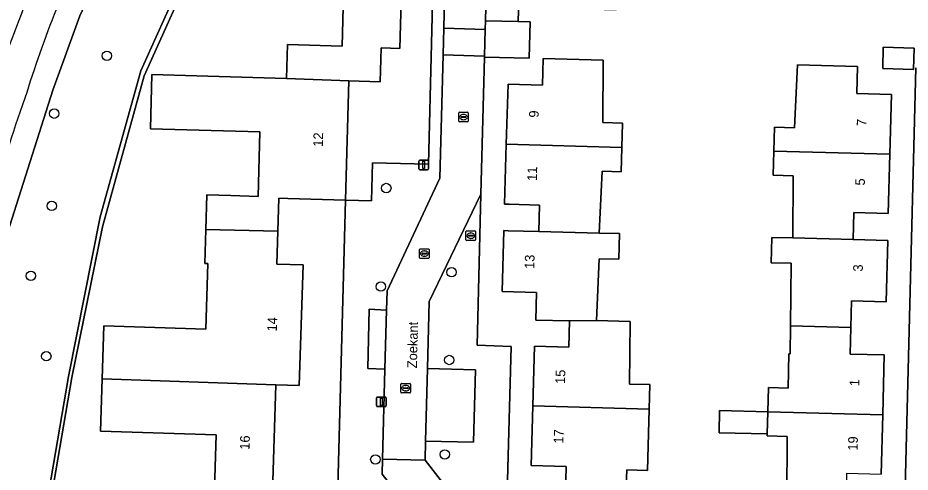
# Model space of a CAD drawing. Extents: x 162082 to 163401, y 388089 to 388636.
# Drawn here: x 162155.2 to 162248, y 388192.8 to 388240.1 of the extents above; entities that cross this region are included whole.
import ezdxf

# ---------------------------------------------------------------- set-up
doc = ezdxf.new("R2010")
doc.units = 0
for name, color, linetype in [('IMGEO_Berm_groen', 7, 'Continuous'), ('IMGEO_Boom', 7, 'Continuous'), ('IMGEO_Brandkraan', 7, 'Continuous'), ('IMGEO_Erf', 7, 'Continuous'), ('IMGEO_Fietspad_gesloten', 7, 'Continuous'), ('IMGEO_Groenvoorziening', 7, 'Continuous'), ('IMGEO_Kolk', 7, 'Continuous'), ('IMGEO_Lichtmast', 7, 'Continuous'), ('IMGEO_Muur', 7, 'Continuous'), ('IMGEO_Openbare_ruimte_label', 7, 'Continuous'), ('IMGEO_Pand', 7, 'Continuous'), ('IMGEO_Pand_nummerreeks', 7, 'Continuous'), ('IMGEO_Parkeervlak_open', 7, 'Continuous'), ('IMGEO_Rijbaan_lokaal_open', 7, 'Continuous'), ('IMGEO_Voetpad_open', 7, 'Continuous')]:
    doc.layers.add(name, color=color, linetype=linetype)

msp = doc.modelspace()

# ---------------------------------------------------------------- linework, layer by layer
at = {"layer": 'IMGEO_Berm_groen'}
for points in [[(162157.762, 388186.972), (162160.453, 388202.779), (162163.757, 388219.4), (162167.977, 388234.595), (162172.103, 388243.782), (162172.009, 388243.827), (162174.687, 388249.789), (162174.799, 388249.786), (162177.085, 388254.875), (162185.012, 388266.817), (162192.618, 388276.468), (162195.788, 388280.075), (162202.082, 388286.205), (162199.498, 388288.679), (162206.339, 388296.126), (162204.757, 388297.619), (162216.729, 388310.598)], [(162207.657, 388306.004), (162193.849, 388291.667), (162195.833, 388289.739), (162185.601, 388278.37), (162179.303, 388271.066), (162173.82, 388263.104), (162169.541, 388255.855), (162166.315, 388250), (162165.112, 388247.818), (162161.634, 388240.291), (162158.829, 388232.574), (162153.616, 388216.204), (162152.635, 388208.277), (162153.36, 388204.265), (162153.504, 388199.591), (162151.506, 388186.435)]]:
    msp.add_lwpolyline(points, dxfattribs=at)
msp.add_arc((162273.166, 388193.916), 126.504, 155.33064, 165.20021, dxfattribs=at)
at = {"layer": 'IMGEO_Boom'}
for centre in [(162164.44, 388236.151), (162158.966, 388230.129), (162193.502, 388222.392), (162158.707, 388220.536), (162156.535, 388213.27), (162200.287, 388213.64), (162192.947, 388212.142), (162158.143, 388204.9), (162200.053, 388204.506), (162199.581, 388194.687), (162192.363, 388194.159)]:
    msp.add_circle(centre, 0.489, dxfattribs=at)
at = {"layer": 'IMGEO_Brandkraan'}
for p, q in [((162201.862, 388217.937), (162202.714, 388217.937)), ((162201.787, 388217.011), (162201.787, 388217.863)), ((162202.046, 388217.431), (162202.046, 388217.443)), ((162202.484, 388217.394), (162202.086, 388217.394)), ((162202.089, 388217.48), (162202.487, 388217.48)), ((162202.298, 388217.157), (162202.273, 388217.157)), ((162202.275, 388217.717), (162202.3, 388217.717)), ((162202.53, 388217.443), (162202.53, 388217.431)), ((162202.788, 388217.863), (162202.788, 388217.011)), ((162202.714, 388216.937), (162201.862, 388216.937))]:
    msp.add_line(p, q, dxfattribs=at)
for points in [[(162201.862, 388217.937), (162202.714, 388217.937)], [(162201.787, 388217.011), (162201.787, 388217.863)], [(162202.788, 388217.863), (162202.788, 388217.011)], [(162202.714, 388216.937), (162201.862, 388216.937)]]:
    msp.add_lwpolyline(points, dxfattribs=at)
for centre, radius, start, end in [((162201.864, 388217.861), 0.0765, 91.55205, 178.44795), ((162201.864, 388217.861), 0.0765, 91.55205, 178.44795), ((162202.712, 388217.861), 0.0765, 1.55205, 88.44795), ((162202.712, 388217.861), 0.0765, 1.55205, 88.44795), ((162201.864, 388217.013), 0.0765, 181.55205, 268.44795), ((162201.864, 388217.013), 0.0765, 181.55205, 268.44795), ((162202.086, 388217.44), 0.0403, 85.87752, 175.75265), ((162202.083, 388217.43), 0.0366, 178.93798, 274.71019), ((162202.487, 388217.437), 0.043, 264.86636, 352.45326), ((162202.491, 388217.442), 0.0386, 1.73085, 96.63898), ((162202.712, 388217.013), 0.0765, 271.55205, 358.44795), ((162202.712, 388217.013), 0.0765, 271.55205, 358.44795)]:
    msp.add_arc(centre, radius, start, end, dxfattribs=at)
for centre, major_axis, ratio, start_param, end_param in [((162202.274, 388217.437), (-0.387, 0.002), 0.722429, 4.712389, 7.853982), ((162202.299, 388217.437), (-0.39, 0.002), 0.717154, 1.570796, 4.712389)]:
    msp.add_ellipse(centre, major_axis=major_axis, ratio=ratio, start_param=start_param, end_param=end_param, dxfattribs=at)
at = {"layer": 'IMGEO_Erf'}
for points in [[(162195.256, 388249.225), (162194.905, 388236.916), (162192.964, 388236.972), (162192.864, 388233.447), (162189.615, 388233.54), (162189.261, 388221.138), (162191.96, 388221.062), (162192.072, 388225.007), (162197.898, 388224.865), (162198.526, 388250)], [(162175.609, 388189.983), (162175.823, 388196.73), (162163.788, 388197.112), (162163.96, 388202.542), (162164.135, 388208.05), (162174.724, 388207.714), (162174.94, 388214.538), (162174.621, 388214.548), (162174.733, 388218.078), (162174.847, 388221.689), (162177.326, 388221.61), (162180.165, 388221.52), (162180.356, 388228.234), (162168.964, 388228.559), (162169.125, 388234.186), (162183.13, 388233.787), (162183.23, 388237.319), (162188.906, 388237.157), (162189.099, 388243.93)], [(162172.591, 388243.552), (162168.323, 388234.056), (162163.98, 388218.368), (162160.807, 388202.671), (162158.079, 388186.902)], [(162207.325, 388243.257), (162207.23, 388239.701), (162208.459, 388239.668), (162208.358, 388235.884), (162203.706, 388236.008), (162203.345, 388221.743), (162202.944, 388206.041), (162206.472, 388205.907), (162206.087, 388190.715)], [(162212.126, 388190.638), (162212.205, 388193.419), (162208.567, 388193.522), (162208.742, 388199.747), (162208.916, 388205.928), (162212.49, 388205.827), (162212.568, 388208.567), (162209.049, 388208.666), (162209.129, 388211.517), (162205.541, 388211.618), (162205.72, 388217.964), (162206.19, 388217.951), (162209.362, 388217.862), (162209.44, 388220.62), (162206.279, 388220.709), (162205.809, 388220.722), (162205.985, 388226.955), (162206.16, 388233.186), (162209.739, 388233.086), (162209.818, 388235.864), (162214.817, 388235.723), (162216.069, 388235.688), (162216.039, 388229.194), (162218.074, 388229.137), (162218.002, 388226.614), (162217.931, 388224.091), (162215.94, 388224.147), (162215.639, 388217.715), (162217.77, 388217.655), (162217.695, 388214.979), (162215.648, 388215.037), (162215.366, 388208.617), (162218.86, 388208.519), (162218.791, 388202.001), (162220.92, 388201.941), (162220.849, 388199.408), (162220.778, 388196.875), (162220.669, 388193.016), (162218.521, 388193.077), (162218.402, 388190.462)], [(162235.149, 388190.087), (162235.185, 388196.562), (162233.108, 388196.617), (162233.113, 388196.814), (162228.113, 388196.946), (162228.174, 388199.263), (162233.174, 388199.131), (162233.241, 388201.645), (162235.283, 388201.591), (162235.378, 388205.15), (162235.492, 388205.147), (162235.533, 388208.057), (162235.626, 388214.563), (162233.545, 388214.618), (162233.615, 388217.262), (162235.78, 388217.204), (162235.835, 388223.667), (162233.745, 388223.723), (162233.811, 388226.22), (162233.877, 388228.718), (162235.958, 388228.663), (162236.257, 388235.211), (162237.516, 388235.178), (162242.514, 388235.045), (162242.439, 388232.224), (162246.039, 388232.128), (162245.874, 388225.902), (162245.711, 388219.759), (162242.124, 388219.854), (162242.049, 388217.026), (162245.661, 388216.931), (162245.492, 388210.56), (162241.893, 388210.655), (162241.819, 388207.89), (162241.746, 388205.126), (162245.299, 388205.032), (162245.135, 388198.815), (162244.971, 388192.631)], [(162247.444, 388189.812), (162248.593, 388234.883)], [(162188.209, 388182.234), (162189.261, 388221.138), (162183.262, 388221.309), (162182.319, 388221.336), (162182.211, 388217.911), (162182.102, 388214.475), (162184.853, 388214.387), (162184.456, 388201.851), (162182.005, 388201.929), (162181.617, 388189.702)]]:
    msp.add_lwpolyline(points, dxfattribs=at)
msp.add_lwpolyline([(162245.129, 388234.822), (162245.188, 388237.034), (162248.407, 388236.948), (162248.348, 388234.736)], close=True, dxfattribs=at)
at = {"layer": 'IMGEO_Fietspad_gesloten'}
for centre, radius, start, end in [((162272.303, 388195.984), 121.751, 153.66232, 162.91897), ((162273.166, 388193.916), 126.504, 155.33064, 165.20021), ((162244.129, 388199.115), 94.049, 159.69961, 173.99707)]:
    msp.add_arc(centre, radius, start, end, dxfattribs=at)
at = {"layer": 'IMGEO_Groenvoorziening'}
msp.add_lwpolyline([(162156.818, 388168.551), (162155.992, 388168.648), (162155.548, 388168.732), (162155.641, 388169.499), (162149.29, 388170.484), (162151.506, 388186.435), (162153.504, 388199.591), (162153.36, 388204.265), (162152.635, 388208.277), (162153.616, 388216.204), (162158.829, 388232.574), (162161.634, 388240.291), (162165.112, 388247.818), (162166.315, 388250), (162169.541, 388255.855), (162173.82, 388263.104), (162179.303, 388271.066), (162185.601, 388278.37), (162195.833, 388289.739), (162193.849, 388291.667), (162191.53, 388289.26)], dxfattribs=at)
for centre, radius, start, end in [((162272.303, 388195.984), 121.751, 153.66232, 162.91897), ((162244.129, 388199.115), 94.049, 159.69961, 173.99707)]:
    msp.add_arc(centre, radius, start, end, dxfattribs=at)
at = {"layer": 'IMGEO_Kolk'}
for p, q in [((162201.029, 388229.348), (162201.029, 388230.2)), ((162201.104, 388230.274), (162201.956, 388230.274)), ((162201.517, 388230.054), (162201.542, 388230.054)), ((162202.03, 388230.2), (162202.03, 388229.348)), ((162201.956, 388229.274), (162201.104, 388229.274)), ((162201.288, 388229.768), (162201.288, 388229.78)), ((162201.726, 388229.731), (162201.328, 388229.731)), ((162201.331, 388229.817), (162201.729, 388229.817)), ((162201.54, 388229.494), (162201.515, 388229.494)), ((162201.772, 388229.78), (162201.772, 388229.768)), ((162197.036, 388216.072), (162197.888, 388216.072)), ((162196.961, 388215.146), (162196.961, 388215.998)), ((162197.22, 388215.566), (162197.22, 388215.578)), ((162197.658, 388215.529), (162197.26, 388215.529)), ((162197.263, 388215.615), (162197.661, 388215.615)), ((162197.472, 388215.292), (162197.447, 388215.292)), ((162197.449, 388215.852), (162197.474, 388215.852)), ((162197.704, 388215.578), (162197.704, 388215.566)), ((162197.962, 388215.998), (162197.962, 388215.146)), ((162197.888, 388215.072), (162197.036, 388215.072)), ((162195.019, 388201.152), (162195.019, 388202.004)), ((162195.094, 388202.078), (162195.946, 388202.078)), ((162195.278, 388201.572), (162195.278, 388201.584)), ((162195.716, 388201.535), (162195.318, 388201.535)), ((162195.321, 388201.621), (162195.719, 388201.621)), ((162195.53, 388201.298), (162195.505, 388201.298)), ((162195.507, 388201.858), (162195.532, 388201.858)), ((162195.762, 388201.584), (162195.762, 388201.572)), ((162196.02, 388202.004), (162196.02, 388201.152)), ((162195.946, 388201.078), (162195.094, 388201.078))]:
    msp.add_line(p, q, dxfattribs=at)
for points in [[(162201.029, 388229.348), (162201.029, 388230.2)], [(162201.104, 388230.274), (162201.956, 388230.274)], [(162202.03, 388230.2), (162202.03, 388229.348)], [(162201.956, 388229.274), (162201.104, 388229.274)], [(162197.036, 388216.072), (162197.888, 388216.072)], [(162196.961, 388215.146), (162196.961, 388215.998)], [(162197.962, 388215.998), (162197.962, 388215.146)], [(162197.888, 388215.072), (162197.036, 388215.072)], [(162195.019, 388201.152), (162195.019, 388202.004)], [(162195.094, 388202.078), (162195.946, 388202.078)], [(162196.02, 388202.004), (162196.02, 388201.152)], [(162195.946, 388201.078), (162195.094, 388201.078)]]:
    msp.add_lwpolyline(points, dxfattribs=at)
for centre, radius, start, end in [((162201.106, 388230.198), 0.0765, 91.55205, 178.44795), ((162201.106, 388230.198), 0.0765, 91.55205, 178.44795), ((162201.954, 388230.198), 0.0765, 1.55205, 88.44795), ((162201.954, 388230.198), 0.0765, 1.55205, 88.44795), ((162201.106, 388229.35), 0.0765, 181.55205, 268.44795), ((162201.106, 388229.35), 0.0765, 181.55205, 268.44795), ((162201.328, 388229.777), 0.0403, 85.87752, 175.75265), ((162201.325, 388229.767), 0.0366, 178.93798, 274.71019), ((162201.729, 388229.774), 0.043, 264.86636, 352.45326), ((162201.733, 388229.779), 0.0386, 1.73085, 96.63898), ((162201.954, 388229.35), 0.0765, 271.55205, 358.44795), ((162201.954, 388229.35), 0.0765, 271.55205, 358.44795), ((162197.038, 388215.996), 0.0765, 91.55205, 178.44795), ((162197.038, 388215.996), 0.0765, 91.55205, 178.44795), ((162197.886, 388215.996), 0.0765, 1.55205, 88.44795), ((162197.886, 388215.996), 0.0765, 1.55205, 88.44795), ((162197.038, 388215.148), 0.0765, 181.55205, 268.44795), ((162197.038, 388215.148), 0.0765, 181.55205, 268.44795), ((162197.26, 388215.575), 0.0403, 85.87752, 175.75265), ((162197.257, 388215.565), 0.0366, 178.93798, 274.71019), ((162197.661, 388215.572), 0.043, 264.86636, 352.45326), ((162197.665, 388215.577), 0.0386, 1.73085, 96.63898), ((162197.886, 388215.148), 0.0765, 271.55205, 358.44795), ((162197.886, 388215.148), 0.0765, 271.55205, 358.44795), ((162195.096, 388202.002), 0.0765, 91.55205, 178.44795), ((162195.096, 388202.002), 0.0765, 91.55205, 178.44795), ((162195.318, 388201.581), 0.0403, 85.87752, 175.75265), ((162195.315, 388201.571), 0.0366, 178.93798, 274.71019), ((162195.719, 388201.578), 0.043, 264.86636, 352.45326), ((162195.723, 388201.583), 0.0386, 1.73085, 96.63898), ((162195.944, 388202.002), 0.0765, 1.55205, 88.44795), ((162195.944, 388202.002), 0.0765, 1.55205, 88.44795), ((162195.096, 388201.154), 0.0765, 181.55205, 268.44795), ((162195.096, 388201.154), 0.0765, 181.55205, 268.44795), ((162195.944, 388201.154), 0.0765, 271.55205, 358.44795), ((162195.944, 388201.154), 0.0765, 271.55205, 358.44795)]:
    msp.add_arc(centre, radius, start, end, dxfattribs=at)
for centre, major_axis, ratio, start_param, end_param in [((162201.516, 388229.774), (-0.387, 0.002), 0.722429, 4.712389, 7.853982), ((162201.541, 388229.774), (-0.39, 0.002), 0.717154, 1.570796, 4.712389), ((162197.448, 388215.572), (-0.387, 0.002), 0.722429, 4.712389, 7.853982), ((162197.473, 388215.572), (-0.39, 0.002), 0.717154, 1.570796, 4.712389), ((162195.506, 388201.578), (-0.387, 0.002), 0.722429, 4.712389, 7.853982), ((162195.531, 388201.578), (-0.39, 0.002), 0.717154, 1.570796, 4.712389)]:
    msp.add_ellipse(centre, major_axis=major_axis, ratio=ratio, start_param=start_param, end_param=end_param, dxfattribs=at)
at = {"layer": 'IMGEO_Lichtmast'}
for p, q in [((162196.895, 388224.397), (162196.895, 388225.197)), ((162196.895, 388225.197), (162196.895, 388224.397)), ((162196.995, 388225.297), (162197.785, 388225.297)), ((162197.785, 388225.297), (162196.995, 388225.297)), ((162197.885, 388225.197), (162197.885, 388224.397)), ((162197.885, 388224.397), (162197.885, 388225.197)), ((162197.785, 388224.297), (162196.995, 388224.297)), ((162196.995, 388224.297), (162197.785, 388224.297)), ((162192.493, 388199.757), (162192.493, 388200.557)), ((162192.493, 388200.557), (162192.493, 388199.757)), ((162192.593, 388200.657), (162193.383, 388200.657)), ((162193.383, 388200.657), (162192.593, 388200.657)), ((162193.483, 388200.557), (162193.483, 388199.757)), ((162193.483, 388199.757), (162193.483, 388200.557)), ((162193.383, 388199.657), (162192.593, 388199.657)), ((162192.593, 388199.657), (162193.383, 388199.657))]:
    msp.add_line(p, q, dxfattribs=at)
for points in [[(162197.315, 388225.172), (162197.465, 388225.172), (162197.465, 388224.422), (162197.315, 388224.422), (162197.315, 388225.172)], [(162192.913, 388200.532), (162193.063, 388200.532), (162193.063, 388199.782), (162192.913, 388199.782), (162192.913, 388200.532)]]:
    msp.add_lwpolyline(points, dxfattribs=at)
for centre, start, end in [((162196.995, 388225.197), 90, 180), ((162196.995, 388225.197), 90, 180), ((162197.785, 388225.197), 0, 90), ((162197.785, 388225.197), 360, 90), ((162196.995, 388224.397), 180, 270), ((162196.995, 388224.397), 180, 270), ((162197.785, 388224.397), 270, 0), ((162197.785, 388224.397), 270, 0), ((162192.593, 388200.557), 90, 180), ((162192.593, 388200.557), 90, 180), ((162193.383, 388200.557), 0, 90), ((162193.383, 388200.557), 360, 90), ((162192.593, 388199.757), 180, 270), ((162192.593, 388199.757), 180, 270), ((162193.383, 388199.757), 270, 0), ((162193.383, 388199.757), 270, 0)]:
    msp.add_arc(centre, 0.1, start, end, dxfattribs=at)
at = {"layer": 'IMGEO_Muur'}
msp.add_lwpolyline([(162168.323, 388234.056), (162172.591, 388243.552), (162172.103, 388243.782), (162167.977, 388234.595), (162163.757, 388219.4), (162160.453, 388202.779), (162157.762, 388186.972), (162155.641, 388169.499), (162155.548, 388168.732), (162155.992, 388168.648), (162158.079, 388186.902), (162160.807, 388202.671), (162163.98, 388218.368)], close=True, dxfattribs=at)
at = {"layer": 'IMGEO_Pand'}
for points in [[(162217.729, 388253.009), (162211.462, 388253.177), (162211.378, 388250), (162211.367, 388249.592), (162204.074, 388249.786), (162203.807, 388239.792), (162207.23, 388239.701), (162207.325, 388243.257), (162214.931, 388243.054), (162214.875, 388240.981), (162217.406, 388240.913), (162217.649, 388250)], [(162195.256, 388249.225), (162177.679, 388249.707), (162175.385, 388249.77), (162174.799, 388249.786), (162174.687, 388249.789), (162172.009, 388243.827), (162172.103, 388243.782), (162172.591, 388243.552), (162175.572, 388242.141), (162176.763, 388242.099), (162177.707, 388242.955), (162177.701, 388244.255), (162189.099, 388243.93), (162188.906, 388237.157), (162183.23, 388237.319), (162183.13, 388233.787), (162189.615, 388233.54), (162192.864, 388233.447), (162192.964, 388236.972), (162194.905, 388236.916)], [(162207.23, 388239.701), (162203.807, 388239.792), (162203.783, 388238.893), (162203.709, 388236.124), (162203.706, 388236.008), (162208.358, 388235.884), (162208.459, 388239.668)], [(162245.129, 388234.822), (162248.348, 388234.736), (162248.407, 388236.948), (162245.188, 388237.034)], [(162205.985, 388226.955), (162218.002, 388226.614), (162218.074, 388229.137), (162216.039, 388229.194), (162216.069, 388235.688), (162214.817, 388235.723), (162209.818, 388235.864), (162209.739, 388233.086), (162206.16, 388233.186)], [(162233.811, 388226.22), (162245.874, 388225.902), (162246.039, 388232.128), (162242.439, 388232.224), (162242.514, 388235.045), (162237.516, 388235.178), (162236.257, 388235.211), (162235.958, 388228.663), (162233.877, 388228.718)], [(162189.615, 388233.54), (162183.13, 388233.787), (162169.125, 388234.186), (162168.964, 388228.559), (162180.356, 388228.234), (162180.165, 388221.52), (162177.326, 388221.61), (162174.847, 388221.689), (162174.733, 388218.078), (162182.211, 388217.911), (162182.319, 388221.336), (162183.262, 388221.309), (162189.261, 388221.138)], [(162209.362, 388217.862), (162215.639, 388217.715), (162215.94, 388224.147), (162217.931, 388224.091), (162218.002, 388226.614), (162205.985, 388226.955), (162205.809, 388220.722), (162206.279, 388220.709), (162209.44, 388220.62)], [(162235.78, 388217.204), (162242.049, 388217.026), (162242.124, 388219.854), (162245.711, 388219.759), (162245.874, 388225.902), (162233.811, 388226.22), (162233.745, 388223.723), (162235.835, 388223.667)], [(162184.853, 388214.387), (162182.102, 388214.475), (162182.211, 388217.911), (162174.733, 388218.078), (162174.621, 388214.548), (162174.94, 388214.538), (162174.724, 388207.714), (162164.135, 388208.05), (162163.96, 388202.542), (162182.005, 388201.929), (162184.456, 388201.851)], [(162212.568, 388208.567), (162215.366, 388208.617), (162215.648, 388215.037), (162217.695, 388214.979), (162217.77, 388217.655), (162215.639, 388217.715), (162209.362, 388217.862), (162206.19, 388217.951), (162205.72, 388217.964), (162205.541, 388211.618), (162209.129, 388211.517), (162209.049, 388208.666)], [(162235.78, 388217.204), (162233.615, 388217.262), (162233.545, 388214.618), (162235.626, 388214.563), (162235.533, 388208.057), (162241.819, 388207.89), (162241.893, 388210.655), (162245.492, 388210.56), (162245.661, 388216.931), (162242.049, 388217.026)], [(162212.568, 388208.567), (162212.49, 388205.827), (162208.916, 388205.928), (162208.742, 388199.747), (162220.849, 388199.408), (162220.92, 388201.941), (162218.791, 388202.001), (162218.86, 388208.519), (162215.366, 388208.617)], [(162233.174, 388199.131), (162245.135, 388198.815), (162245.299, 388205.032), (162241.746, 388205.126), (162241.819, 388207.89), (162235.533, 388208.057), (162235.492, 388205.147), (162235.378, 388205.15), (162235.283, 388201.591), (162233.241, 388201.645)], [(162163.788, 388197.112), (162175.823, 388196.73), (162175.609, 388189.983), (162170.122, 388190.157), (162170.01, 388186.629), (162177.566, 388186.402), (162177.674, 388189.827), (162181.617, 388189.702), (162182.005, 388201.929), (162163.96, 388202.542)], [(162220.849, 388199.408), (162208.742, 388199.747), (162208.567, 388193.522), (162212.205, 388193.419), (162212.126, 388190.638), (162218.402, 388190.462), (162218.521, 388193.077), (162220.669, 388193.016), (162220.778, 388196.875)], [(162233.174, 388199.131), (162228.174, 388199.263), (162228.113, 388196.946), (162233.113, 388196.814)], [(162245.135, 388198.815), (162233.174, 388199.131), (162233.113, 388196.814), (162233.108, 388196.617), (162235.185, 388196.562), (162235.149, 388190.087), (162241.342, 388189.923), (162241.416, 388192.725), (162244.971, 388192.631)]]:
    msp.add_lwpolyline(points, close=True, dxfattribs=at)
at = {"layer": 'IMGEO_Parkeervlak_open'}
for points in [[(162193.526, 388209.687), (162191.729, 388209.785), (162191.567, 388203.624), (162193.366, 388203.564)], [(162197.588, 388196.062), (162202.576, 388195.956), (162202.764, 388203.494), (162197.788, 388203.634)]]:
    msp.add_lwpolyline(points, close=True, dxfattribs=at)
at = {"layer": 'IMGEO_Rijbaan_lokaal_open'}
for points in [[(162204.074, 388249.786), (162204.08, 388250), (162204.241, 388255.823), (162199.889, 388255.931), (162199.742, 388250), (162199.47, 388239.004), (162203.783, 388238.893), (162203.807, 388239.792)], [(162203.783, 388238.893), (162199.47, 388239.004), (162199.401, 388236.235), (162203.709, 388236.124)], [(162203.345, 388221.743), (162203.706, 388236.008), (162203.709, 388236.124), (162199.401, 388236.235), (162199.084, 388223.422), (162193.579, 388211.712), (162193.526, 388209.687), (162193.366, 388203.564), (162193.114, 388194.2), (162197.54, 388194.081), (162197.588, 388196.062), (162197.788, 388203.634), (162197.969, 388210.593)], [(162247.424, 388188.529), (162206.058, 388189.507), (162201.028, 388189.626), (162197.54, 388194.081), (162193.114, 388194.2), (162193.072, 388192.624), (162198.816, 388185.29), (162202.738, 388185.187), (162208.745, 388185.028), (162225.315, 388184.591), (162237.373, 388184.273), (162247.313, 388184.011)]]:
    msp.add_lwpolyline(points, close=True, dxfattribs=at)
at = {"layer": 'IMGEO_Voetpad_open'}
for points in [[(162199.742, 388250), (162199.889, 388255.931), (162199.959, 388258.772), (162199.97, 388259.135), (162198.755, 388259.165), (162198.526, 388250), (162197.898, 388224.865), (162192.072, 388225.007), (162191.96, 388221.062), (162189.261, 388221.138), (162188.209, 388182.234), (162198.727, 388181.955), (162198.816, 388185.29), (162193.072, 388192.624), (162193.114, 388194.2), (162193.366, 388203.564), (162191.567, 388203.624), (162191.729, 388209.785), (162193.526, 388209.687), (162193.579, 388211.712), (162199.084, 388223.422), (162199.401, 388236.235), (162199.47, 388239.004)], [(162206.472, 388205.907), (162202.944, 388206.041), (162203.345, 388221.743), (162197.969, 388210.593), (162197.788, 388203.634), (162202.764, 388203.494), (162202.576, 388195.956), (162197.588, 388196.062), (162197.54, 388194.081), (162201.028, 388189.626), (162206.058, 388189.507), (162206.087, 388190.715)]]:
    msp.add_lwpolyline(points, close=True, dxfattribs=at)
msp.add_lwpolyline([(162248.593, 388234.883), (162247.444, 388189.812), (162247.424, 388188.529), (162247.313, 388184.011), (162247.194, 388180.668), (162247.082, 388176.455), (162246.886, 388168.967), (162246.603, 388158.397), (162246.31, 388156.172), (162246.253, 388155.203), (162247.139, 388155.135)], dxfattribs=at)

# ---------------------------------------------------------------- texts
at = {"layer": 'IMGEO_Openbare_ruimte_label'}
msp.add_text('Zoekant', height=1, rotation=88.51065, dxfattribs=at).set_placement((162196.683, 388203.638))
at = {"layer": 'IMGEO_Pand_nummerreeks'}
for s, rotation, p in [('9', 88.38691, (162209.343, 388229.702)), ('7', 88.48099, (162243.431, 388228.827)), ('12', 88.36501, (162186.898, 388226.673)), ('11', 88.38691, (162209.158, 388223.124)), ('5', 88.48099, (162243.267, 388222.642)), ('13', 88.3843, (162208.888, 388213.963)), ('3', 88.4805, (162243.055, 388213.691)), ('14', 88.18393, (162182.112, 388207.464)), ('15', 88.38861, (162212.087, 388201.999)), ('1', 88.48491, (162242.692, 388201.763)), ('16', 88.18244, (162179.268, 388195.16)), ('17', 88.3902, (162211.912, 388195.796)), ('19', 88.4876, (162242.515, 388195.064))]:
    msp.add_text(s, height=1, rotation=rotation, dxfattribs=at).set_placement(p)

doc.saveas('drawing.dxf')
